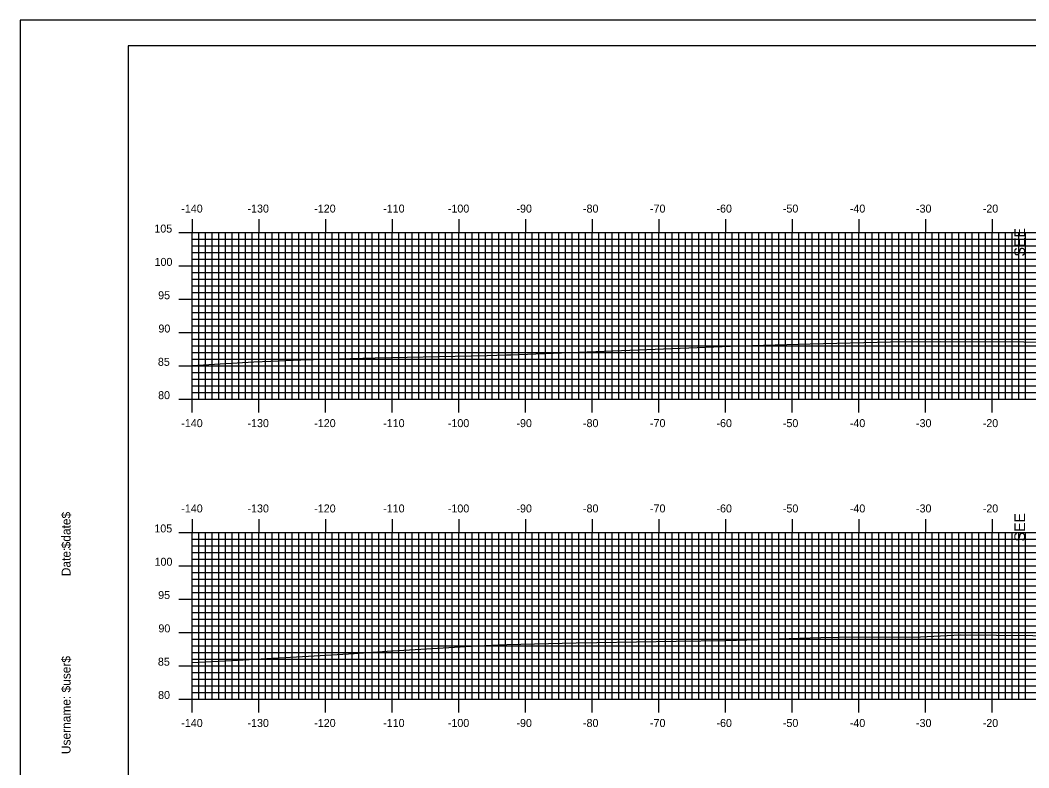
# Model space of a CAD drawing. Extents: x 1272 to 1616, y -1658 to -1438.
# Drawn here: x 1272.4 to 1423.7, y -1549.9 to -1437.7 of the extents above; entities that cross this region are included whole.
import ezdxf

# ---------------------------------------------------------------- set-up
doc = ezdxf.new("R2010")
doc.units = 0
for name, color, linetype in [('ANNOTATION', 7, 'Continuous'), ('BORDER', 7, 'Continuous'), ('H_V ANNOTATION', 7, 'Continuous'), ('MAJOR', 7, 'Continuous'), ('MINOR', 7, 'Continuous'), ('PLOT BOUNDARY', 7, 'Continuous'), ('S_Roadway_Centerline', 7, 'Continuous')]:
    doc.layers.add(name, color=color, linetype=linetype)

msp = doc.modelspace()

# ---------------------------------------------------------------- linework, layer by layer
at = {"layer": 'BORDER'}
msp.add_lwpolyline([(1288.56, -1651.6), (1608.56, -1651.6), (1608.56, -1441.6), (1288.56, -1441.6)], close=True, dxfattribs=at)
at = {"layer": 'MAJOR'}
for p, q in [((1298.16, -1467.6), (1298.16, -1469.6)), ((1308.16, -1467.6), (1308.16, -1469.6)), ((1318.16, -1467.6), (1318.16, -1469.6)), ((1328.16, -1467.6), (1328.16, -1469.6)), ((1338.16, -1467.6), (1338.16, -1469.6)), ((1348.16, -1467.6), (1348.16, -1469.6)), ((1358.16, -1467.6), (1358.16, -1469.6)), ((1368.16, -1467.6), (1368.16, -1469.6)), ((1378.16, -1467.6), (1378.16, -1469.6)), ((1388.16, -1467.6), (1388.16, -1469.6)), ((1398.16, -1467.6), (1398.16, -1469.6)), ((1408.16, -1467.6), (1408.16, -1469.6)), ((1418.16, -1467.6), (1418.16, -1469.6)), ((1296.16, -1469.6), (1298.16, -1469.6)), ((1298.16, -1469.6), (1578.16, -1469.6)), ((1298.16, -1494.6), (1298.16, -1469.6)), ((1298.16, -1494.6), (1298.16, -1469.6)), ((1298.16, -1469.6), (1578.16, -1469.6)), ((1308.16, -1494.6), (1308.16, -1469.6)), ((1318.16, -1494.6), (1318.16, -1469.6)), ((1328.16, -1494.6), (1328.16, -1469.6)), ((1338.16, -1494.6), (1338.16, -1469.6)), ((1348.16, -1494.6), (1348.16, -1469.6)), ((1358.16, -1494.6), (1358.16, -1469.6)), ((1368.16, -1494.6), (1368.16, -1469.6)), ((1378.16, -1494.6), (1378.16, -1469.6)), ((1388.16, -1494.6), (1388.16, -1469.6)), ((1398.16, -1494.6), (1398.16, -1469.6)), ((1408.16, -1494.6), (1408.16, -1469.6)), ((1418.16, -1494.6), (1418.16, -1469.6)), ((1296.16, -1474.6), (1298.16, -1474.6)), ((1298.16, -1474.6), (1578.16, -1474.6)), ((1296.16, -1479.6), (1298.16, -1479.6)), ((1298.16, -1479.6), (1578.16, -1479.6)), ((1296.16, -1484.6), (1298.16, -1484.6)), ((1298.16, -1484.6), (1578.16, -1484.6)), ((1296.16, -1489.6), (1298.16, -1489.6)), ((1298.16, -1489.6), (1578.16, -1489.6)), ((1296.16, -1494.6), (1298.16, -1494.6)), ((1298.16, -1494.6), (1578.16, -1494.6)), ((1298.16, -1494.6), (1578.16, -1494.6)), ((1298.16, -1496.61), (1298.16, -1494.6)), ((1308.16, -1496.61), (1308.16, -1494.6)), ((1318.16, -1496.61), (1318.16, -1494.6)), ((1328.16, -1496.61), (1328.16, -1494.6)), ((1338.16, -1496.61), (1338.16, -1494.6)), ((1348.16, -1496.61), (1348.16, -1494.6)), ((1358.16, -1496.61), (1358.16, -1494.6)), ((1368.16, -1496.61), (1368.16, -1494.6)), ((1378.16, -1496.61), (1378.16, -1494.6)), ((1388.16, -1496.61), (1388.16, -1494.6)), ((1398.16, -1496.61), (1398.16, -1494.6)), ((1408.16, -1496.61), (1408.16, -1494.6)), ((1418.16, -1496.61), (1418.16, -1494.6)), ((1298.16, -1512.6), (1298.16, -1514.6)), ((1308.16, -1512.6), (1308.16, -1514.6)), ((1318.16, -1512.6), (1318.16, -1514.6)), ((1328.16, -1512.6), (1328.16, -1514.6)), ((1338.16, -1512.6), (1338.16, -1514.6)), ((1348.16, -1512.6), (1348.16, -1514.6)), ((1358.16, -1512.6), (1358.16, -1514.6)), ((1368.16, -1512.6), (1368.16, -1514.6)), ((1378.16, -1512.6), (1378.16, -1514.6)), ((1388.16, -1512.6), (1388.16, -1514.6)), ((1398.16, -1512.6), (1398.16, -1514.6)), ((1408.16, -1512.6), (1408.16, -1514.6)), ((1418.16, -1512.6), (1418.16, -1514.6)), ((1296.16, -1514.6), (1298.16, -1514.6)), ((1298.16, -1514.6), (1578.16, -1514.6)), ((1298.16, -1539.6), (1298.16, -1514.6)), ((1298.16, -1539.6), (1298.16, -1514.6)), ((1298.16, -1514.6), (1578.16, -1514.6)), ((1308.16, -1539.6), (1308.16, -1514.6)), ((1318.16, -1539.6), (1318.16, -1514.6)), ((1328.16, -1539.6), (1328.16, -1514.6)), ((1338.16, -1539.6), (1338.16, -1514.6)), ((1348.16, -1539.6), (1348.16, -1514.6)), ((1358.16, -1539.6), (1358.16, -1514.6)), ((1368.16, -1539.6), (1368.16, -1514.6)), ((1378.16, -1539.6), (1378.16, -1514.6)), ((1388.16, -1539.6), (1388.16, -1514.6)), ((1398.16, -1539.6), (1398.16, -1514.6)), ((1408.16, -1539.6), (1408.16, -1514.6)), ((1418.16, -1539.6), (1418.16, -1514.6)), ((1296.16, -1519.6), (1298.16, -1519.6)), ((1298.16, -1519.6), (1578.16, -1519.6)), ((1296.16, -1524.6), (1298.16, -1524.6)), ((1298.16, -1524.6), (1578.16, -1524.6)), ((1296.16, -1529.6), (1298.16, -1529.6)), ((1298.16, -1529.6), (1578.16, -1529.6)), ((1296.16, -1534.6), (1298.16, -1534.6)), ((1298.16, -1534.6), (1578.16, -1534.6)), ((1296.16, -1539.6), (1298.16, -1539.6)), ((1298.16, -1539.6), (1578.16, -1539.6)), ((1298.16, -1539.6), (1578.16, -1539.6)), ((1298.16, -1541.61), (1298.16, -1539.6)), ((1308.16, -1541.61), (1308.16, -1539.6)), ((1318.16, -1541.61), (1318.16, -1539.6)), ((1328.16, -1541.61), (1328.16, -1539.6)), ((1338.16, -1541.61), (1338.16, -1539.6)), ((1348.16, -1541.61), (1348.16, -1539.6)), ((1358.16, -1541.61), (1358.16, -1539.6)), ((1368.16, -1541.61), (1368.16, -1539.6)), ((1378.16, -1541.61), (1378.16, -1539.6)), ((1388.16, -1541.61), (1388.16, -1539.6)), ((1398.16, -1541.61), (1398.16, -1539.6)), ((1408.16, -1541.61), (1408.16, -1539.6)), ((1418.16, -1541.61), (1418.16, -1539.6))]:
    msp.add_line(p, q, dxfattribs=at)
at = {"layer": 'MINOR'}
for p, q in [((1299.16, -1494.6), (1299.16, -1469.6)), ((1300.16, -1494.6), (1300.16, -1469.6)), ((1301.16, -1494.6), (1301.16, -1469.6)), ((1302.16, -1494.6), (1302.16, -1469.6)), ((1303.16, -1494.6), (1303.16, -1469.6)), ((1304.16, -1494.6), (1304.16, -1469.6)), ((1305.16, -1494.6), (1305.16, -1469.6)), ((1306.16, -1494.6), (1306.16, -1469.6)), ((1307.16, -1494.6), (1307.16, -1469.6)), ((1309.16, -1494.6), (1309.16, -1469.6)), ((1310.16, -1494.6), (1310.16, -1469.6)), ((1311.16, -1494.6), (1311.16, -1469.6)), ((1312.16, -1494.6), (1312.16, -1469.6)), ((1313.16, -1494.6), (1313.16, -1469.6)), ((1314.16, -1494.6), (1314.16, -1469.6)), ((1315.16, -1494.6), (1315.16, -1469.6)), ((1316.16, -1494.6), (1316.16, -1469.6)), ((1317.16, -1494.6), (1317.16, -1469.6)), ((1319.16, -1494.6), (1319.16, -1469.6)), ((1320.16, -1494.6), (1320.16, -1469.6)), ((1321.16, -1494.6), (1321.16, -1469.6)), ((1322.16, -1494.6), (1322.16, -1469.6)), ((1323.16, -1494.6), (1323.16, -1469.6)), ((1324.16, -1494.6), (1324.16, -1469.6)), ((1325.16, -1494.6), (1325.16, -1469.6)), ((1326.16, -1494.6), (1326.16, -1469.6)), ((1327.16, -1494.6), (1327.16, -1469.6)), ((1329.16, -1494.6), (1329.16, -1469.6)), ((1330.16, -1494.6), (1330.16, -1469.6)), ((1331.16, -1494.6), (1331.16, -1469.6)), ((1332.16, -1494.6), (1332.16, -1469.6)), ((1333.16, -1494.6), (1333.16, -1469.6)), ((1334.16, -1494.6), (1334.16, -1469.6)), ((1335.16, -1494.6), (1335.16, -1469.6)), ((1336.16, -1494.6), (1336.16, -1469.6)), ((1337.16, -1494.6), (1337.16, -1469.6)), ((1339.16, -1494.6), (1339.16, -1469.6)), ((1340.16, -1494.6), (1340.16, -1469.6)), ((1341.16, -1494.6), (1341.16, -1469.6)), ((1342.16, -1494.6), (1342.16, -1469.6)), ((1343.16, -1494.6), (1343.16, -1469.6)), ((1344.16, -1494.6), (1344.16, -1469.6)), ((1345.16, -1494.6), (1345.16, -1469.6)), ((1346.16, -1494.6), (1346.16, -1469.6)), ((1347.16, -1494.6), (1347.16, -1469.6)), ((1349.16, -1494.6), (1349.16, -1469.6)), ((1350.16, -1494.6), (1350.16, -1469.6)), ((1351.16, -1494.6), (1351.16, -1469.6)), ((1352.16, -1494.6), (1352.16, -1469.6)), ((1353.16, -1494.6), (1353.16, -1469.6)), ((1354.16, -1494.6), (1354.16, -1469.6)), ((1355.16, -1494.6), (1355.16, -1469.6)), ((1356.16, -1494.6), (1356.16, -1469.6)), ((1357.16, -1494.6), (1357.16, -1469.6)), ((1359.16, -1494.6), (1359.16, -1469.6)), ((1360.16, -1494.6), (1360.16, -1469.6)), ((1361.16, -1494.6), (1361.16, -1469.6)), ((1362.16, -1494.6), (1362.16, -1469.6)), ((1363.16, -1494.6), (1363.16, -1469.6)), ((1364.16, -1494.6), (1364.16, -1469.6)), ((1365.16, -1494.6), (1365.16, -1469.6)), ((1366.16, -1494.6), (1366.16, -1469.6)), ((1367.16, -1494.6), (1367.16, -1469.6)), ((1369.16, -1494.6), (1369.16, -1469.6)), ((1370.16, -1494.6), (1370.16, -1469.6)), ((1371.16, -1494.6), (1371.16, -1469.6)), ((1372.16, -1494.6), (1372.16, -1469.6)), ((1373.16, -1494.6), (1373.16, -1469.6)), ((1374.16, -1494.6), (1374.16, -1469.6)), ((1375.16, -1494.6), (1375.16, -1469.6)), ((1376.16, -1494.6), (1376.16, -1469.6)), ((1377.16, -1494.6), (1377.16, -1469.6)), ((1379.16, -1494.6), (1379.16, -1469.6)), ((1380.16, -1494.6), (1380.16, -1469.6)), ((1381.16, -1494.6), (1381.16, -1469.6)), ((1382.16, -1494.6), (1382.16, -1469.6)), ((1383.16, -1494.6), (1383.16, -1469.6)), ((1384.16, -1494.6), (1384.16, -1469.6)), ((1385.16, -1494.6), (1385.16, -1469.6)), ((1386.16, -1494.6), (1386.16, -1469.6)), ((1387.16, -1494.6), (1387.16, -1469.6)), ((1389.16, -1494.6), (1389.16, -1469.6)), ((1390.16, -1494.6), (1390.16, -1469.6)), ((1391.16, -1494.6), (1391.16, -1469.6)), ((1392.16, -1494.6), (1392.16, -1469.6)), ((1393.16, -1494.6), (1393.16, -1469.6)), ((1394.16, -1494.6), (1394.16, -1469.6)), ((1395.16, -1494.6), (1395.16, -1469.6)), ((1396.16, -1494.6), (1396.16, -1469.6)), ((1397.16, -1494.6), (1397.16, -1469.6)), ((1399.16, -1494.6), (1399.16, -1469.6)), ((1400.16, -1494.6), (1400.16, -1469.6)), ((1401.16, -1494.6), (1401.16, -1469.6)), ((1402.16, -1494.6), (1402.16, -1469.6)), ((1403.16, -1494.6), (1403.16, -1469.6)), ((1404.16, -1494.6), (1404.16, -1469.6)), ((1405.16, -1494.6), (1405.16, -1469.6)), ((1406.16, -1494.6), (1406.16, -1469.6)), ((1407.16, -1494.6), (1407.16, -1469.6)), ((1409.16, -1494.6), (1409.16, -1469.6)), ((1410.16, -1494.6), (1410.16, -1469.6)), ((1411.16, -1494.6), (1411.16, -1469.6)), ((1412.16, -1494.6), (1412.16, -1469.6)), ((1413.16, -1494.6), (1413.16, -1469.6)), ((1414.16, -1494.6), (1414.16, -1469.6)), ((1415.16, -1494.6), (1415.16, -1469.6)), ((1416.16, -1494.6), (1416.16, -1469.6)), ((1417.16, -1494.6), (1417.16, -1469.6)), ((1419.16, -1494.6), (1419.16, -1469.6)), ((1420.16, -1494.6), (1420.16, -1469.6)), ((1421.16, -1494.6), (1421.16, -1469.6)), ((1422.16, -1494.6), (1422.16, -1469.6)), ((1423.16, -1494.6), (1423.16, -1469.6)), ((1298.16, -1470.6), (1578.16, -1470.6)), ((1298.16, -1470.6), (1300.16, -1470.6)), ((1298.16, -1471.6), (1578.16, -1471.6)), ((1298.16, -1471.6), (1300.16, -1471.6)), ((1298.16, -1472.6), (1578.16, -1472.6)), ((1298.16, -1472.6), (1300.16, -1472.6)), ((1298.16, -1473.6), (1578.16, -1473.6)), ((1298.16, -1473.6), (1300.16, -1473.6)), ((1298.16, -1475.6), (1578.16, -1475.6)), ((1298.16, -1475.6), (1300.16, -1475.6)), ((1298.16, -1476.6), (1578.16, -1476.6)), ((1298.16, -1476.6), (1300.16, -1476.6)), ((1298.16, -1477.6), (1578.16, -1477.6)), ((1298.16, -1477.6), (1300.16, -1477.6)), ((1298.16, -1478.6), (1578.16, -1478.6)), ((1298.16, -1478.6), (1300.16, -1478.6)), ((1298.16, -1480.6), (1578.16, -1480.6)), ((1298.16, -1480.6), (1300.16, -1480.6)), ((1298.16, -1481.6), (1578.16, -1481.6)), ((1298.16, -1481.6), (1300.16, -1481.6)), ((1298.16, -1482.6), (1578.16, -1482.6)), ((1298.16, -1482.6), (1300.16, -1482.6)), ((1298.16, -1483.6), (1578.16, -1483.6)), ((1298.16, -1483.6), (1300.16, -1483.6)), ((1298.16, -1485.6), (1578.16, -1485.6)), ((1298.16, -1485.6), (1300.16, -1485.6)), ((1298.16, -1486.6), (1578.16, -1486.6)), ((1298.16, -1486.6), (1300.16, -1486.6)), ((1298.16, -1487.6), (1578.16, -1487.6)), ((1298.16, -1487.6), (1300.16, -1487.6)), ((1298.16, -1488.6), (1578.16, -1488.6)), ((1298.16, -1488.6), (1300.16, -1488.6)), ((1298.16, -1490.6), (1578.16, -1490.6)), ((1298.16, -1490.6), (1300.16, -1490.6)), ((1298.16, -1491.6), (1578.16, -1491.6)), ((1298.16, -1491.6), (1300.16, -1491.6)), ((1298.16, -1492.6), (1578.16, -1492.6)), ((1298.16, -1492.6), (1300.16, -1492.6)), ((1298.16, -1493.6), (1578.16, -1493.6)), ((1298.16, -1493.6), (1300.16, -1493.6)), ((1298.16, -1515.6), (1578.16, -1515.6)), ((1298.16, -1515.6), (1300.16, -1515.6)), ((1299.16, -1539.6), (1299.16, -1514.6)), ((1300.16, -1539.6), (1300.16, -1514.6)), ((1301.16, -1539.6), (1301.16, -1514.6)), ((1302.16, -1539.6), (1302.16, -1514.6)), ((1303.16, -1539.6), (1303.16, -1514.6)), ((1304.16, -1539.6), (1304.16, -1514.6)), ((1305.16, -1539.6), (1305.16, -1514.6)), ((1306.16, -1539.6), (1306.16, -1514.6)), ((1307.16, -1539.6), (1307.16, -1514.6)), ((1309.16, -1539.6), (1309.16, -1514.6)), ((1310.16, -1539.6), (1310.16, -1514.6)), ((1311.16, -1539.6), (1311.16, -1514.6)), ((1312.16, -1539.6), (1312.16, -1514.6)), ((1313.16, -1539.6), (1313.16, -1514.6)), ((1314.16, -1539.6), (1314.16, -1514.6)), ((1315.16, -1539.6), (1315.16, -1514.6)), ((1316.16, -1539.6), (1316.16, -1514.6)), ((1317.16, -1539.6), (1317.16, -1514.6)), ((1319.16, -1539.6), (1319.16, -1514.6)), ((1320.16, -1539.6), (1320.16, -1514.6)), ((1321.16, -1539.6), (1321.16, -1514.6)), ((1322.16, -1539.6), (1322.16, -1514.6)), ((1323.16, -1539.6), (1323.16, -1514.6)), ((1324.16, -1539.6), (1324.16, -1514.6)), ((1325.16, -1539.6), (1325.16, -1514.6)), ((1326.16, -1539.6), (1326.16, -1514.6)), ((1327.16, -1539.6), (1327.16, -1514.6)), ((1329.16, -1539.6), (1329.16, -1514.6)), ((1330.16, -1539.6), (1330.16, -1514.6)), ((1331.16, -1539.6), (1331.16, -1514.6)), ((1332.16, -1539.6), (1332.16, -1514.6)), ((1333.16, -1539.6), (1333.16, -1514.6)), ((1334.16, -1539.6), (1334.16, -1514.6)), ((1335.16, -1539.6), (1335.16, -1514.6)), ((1336.16, -1539.6), (1336.16, -1514.6)), ((1337.16, -1539.6), (1337.16, -1514.6)), ((1339.16, -1539.6), (1339.16, -1514.6)), ((1340.16, -1539.6), (1340.16, -1514.6)), ((1341.16, -1539.6), (1341.16, -1514.6)), ((1342.16, -1539.6), (1342.16, -1514.6)), ((1343.16, -1539.6), (1343.16, -1514.6)), ((1344.16, -1539.6), (1344.16, -1514.6)), ((1345.16, -1539.6), (1345.16, -1514.6)), ((1346.16, -1539.6), (1346.16, -1514.6)), ((1347.16, -1539.6), (1347.16, -1514.6)), ((1349.16, -1539.6), (1349.16, -1514.6)), ((1350.16, -1539.6), (1350.16, -1514.6)), ((1351.16, -1539.6), (1351.16, -1514.6)), ((1352.16, -1539.6), (1352.16, -1514.6)), ((1353.16, -1539.6), (1353.16, -1514.6)), ((1354.16, -1539.6), (1354.16, -1514.6)), ((1355.16, -1539.6), (1355.16, -1514.6)), ((1356.16, -1539.6), (1356.16, -1514.6)), ((1357.16, -1539.6), (1357.16, -1514.6)), ((1359.16, -1539.6), (1359.16, -1514.6)), ((1360.16, -1539.6), (1360.16, -1514.6)), ((1361.16, -1539.6), (1361.16, -1514.6)), ((1362.16, -1539.6), (1362.16, -1514.6)), ((1363.16, -1539.6), (1363.16, -1514.6)), ((1364.16, -1539.6), (1364.16, -1514.6)), ((1365.16, -1539.6), (1365.16, -1514.6)), ((1366.16, -1539.6), (1366.16, -1514.6)), ((1367.16, -1539.6), (1367.16, -1514.6)), ((1369.16, -1539.6), (1369.16, -1514.6)), ((1370.16, -1539.6), (1370.16, -1514.6)), ((1371.16, -1539.6), (1371.16, -1514.6)), ((1372.16, -1539.6), (1372.16, -1514.6)), ((1373.16, -1539.6), (1373.16, -1514.6)), ((1374.16, -1539.6), (1374.16, -1514.6)), ((1375.16, -1539.6), (1375.16, -1514.6)), ((1376.16, -1539.6), (1376.16, -1514.6)), ((1377.16, -1539.6), (1377.16, -1514.6)), ((1379.16, -1539.6), (1379.16, -1514.6)), ((1380.16, -1539.6), (1380.16, -1514.6)), ((1381.16, -1539.6), (1381.16, -1514.6)), ((1382.16, -1539.6), (1382.16, -1514.6)), ((1383.16, -1539.6), (1383.16, -1514.6)), ((1384.16, -1539.6), (1384.16, -1514.6)), ((1385.16, -1539.6), (1385.16, -1514.6)), ((1386.16, -1539.6), (1386.16, -1514.6)), ((1387.16, -1539.6), (1387.16, -1514.6)), ((1389.16, -1539.6), (1389.16, -1514.6)), ((1390.16, -1539.6), (1390.16, -1514.6)), ((1391.16, -1539.6), (1391.16, -1514.6)), ((1392.16, -1539.6), (1392.16, -1514.6)), ((1393.16, -1539.6), (1393.16, -1514.6)), ((1394.16, -1539.6), (1394.16, -1514.6)), ((1395.16, -1539.6), (1395.16, -1514.6)), ((1396.16, -1539.6), (1396.16, -1514.6)), ((1397.16, -1539.6), (1397.16, -1514.6)), ((1399.16, -1539.6), (1399.16, -1514.6)), ((1400.16, -1539.6), (1400.16, -1514.6)), ((1401.16, -1539.6), (1401.16, -1514.6)), ((1402.16, -1539.6), (1402.16, -1514.6)), ((1403.16, -1539.6), (1403.16, -1514.6)), ((1404.16, -1539.6), (1404.16, -1514.6)), ((1405.16, -1539.6), (1405.16, -1514.6)), ((1406.16, -1539.6), (1406.16, -1514.6)), ((1407.16, -1539.6), (1407.16, -1514.6)), ((1409.16, -1539.6), (1409.16, -1514.6)), ((1410.16, -1539.6), (1410.16, -1514.6)), ((1411.16, -1539.6), (1411.16, -1514.6)), ((1412.16, -1539.6), (1412.16, -1514.6)), ((1413.16, -1539.6), (1413.16, -1514.6)), ((1414.16, -1539.6), (1414.16, -1514.6)), ((1415.16, -1539.6), (1415.16, -1514.6)), ((1416.16, -1539.6), (1416.16, -1514.6)), ((1417.16, -1539.6), (1417.16, -1514.6)), ((1419.16, -1539.6), (1419.16, -1514.6)), ((1420.16, -1539.6), (1420.16, -1514.6)), ((1421.16, -1539.6), (1421.16, -1514.6)), ((1422.16, -1539.6), (1422.16, -1514.6)), ((1423.16, -1539.6), (1423.16, -1514.6)), ((1298.16, -1516.6), (1578.16, -1516.6)), ((1298.16, -1516.6), (1300.16, -1516.6)), ((1298.16, -1517.6), (1578.16, -1517.6)), ((1298.16, -1517.6), (1300.16, -1517.6)), ((1298.16, -1518.6), (1578.16, -1518.6)), ((1298.16, -1518.6), (1300.16, -1518.6)), ((1298.16, -1520.6), (1578.16, -1520.6)), ((1298.16, -1520.6), (1300.16, -1520.6)), ((1298.16, -1521.6), (1578.16, -1521.6)), ((1298.16, -1521.6), (1300.16, -1521.6)), ((1298.16, -1522.6), (1578.16, -1522.6)), ((1298.16, -1522.6), (1300.16, -1522.6)), ((1298.16, -1523.6), (1578.16, -1523.6)), ((1298.16, -1523.6), (1300.16, -1523.6)), ((1298.16, -1525.6), (1578.16, -1525.6)), ((1298.16, -1525.6), (1300.16, -1525.6)), ((1298.16, -1526.6), (1578.16, -1526.6)), ((1298.16, -1526.6), (1300.16, -1526.6)), ((1298.16, -1527.6), (1578.16, -1527.6)), ((1298.16, -1527.6), (1300.16, -1527.6)), ((1298.16, -1528.6), (1578.16, -1528.6)), ((1298.16, -1528.6), (1300.16, -1528.6)), ((1298.16, -1530.6), (1578.16, -1530.6)), ((1298.16, -1530.6), (1300.16, -1530.6)), ((1298.16, -1531.6), (1578.16, -1531.6)), ((1298.16, -1531.6), (1300.16, -1531.6)), ((1298.16, -1532.6), (1578.16, -1532.6)), ((1298.16, -1532.6), (1300.16, -1532.6)), ((1298.16, -1533.6), (1578.16, -1533.6)), ((1298.16, -1533.6), (1300.16, -1533.6)), ((1298.16, -1535.6), (1578.16, -1535.6)), ((1298.16, -1535.6), (1300.16, -1535.6)), ((1298.16, -1536.6), (1578.16, -1536.6)), ((1298.16, -1536.6), (1300.16, -1536.6)), ((1298.16, -1537.6), (1578.16, -1537.6)), ((1298.16, -1537.6), (1300.16, -1537.6)), ((1298.16, -1538.6), (1578.16, -1538.6)), ((1298.16, -1538.6), (1300.16, -1538.6))]:
    msp.add_line(p, q, dxfattribs=at)
at = {"layer": 'PLOT BOUNDARY'}
msp.add_lwpolyline([(1272.37, -1657.72), (1612.37, -1657.72), (1612.37, -1437.72), (1272.37, -1437.72)], close=True, dxfattribs=at)
at = {"layer": 'S_Roadway_Centerline'}
for points in [[(1298.16, -1489.57), (1298.19, -1489.57), (1307.43, -1489), (1309.98, -1488.88), (1314.49, -1488.71), (1325.64, -1488.38), (1342.41, -1488.04), (1345.3, -1487.96), (1345.97, -1487.93), (1347.17, -1487.89), (1365.12, -1487.18), (1378.93, -1486.65), (1382.04, -1486.54), (1383.87, -1486.51), (1390.85, -1486.29), (1402.89, -1485.98), (1410.44, -1485.94), (1422.9, -1486), (1430.31, -1486.16)], [(1298.16, -1534.12), (1304.06, -1533.83), (1317.35, -1533.07), (1322.46, -1532.75), (1327.44, -1532.42), (1340.88, -1531.63), (1345.37, -1531.42), (1355.79, -1531.19), (1358.86, -1531.14), (1370.78, -1530.9), (1378.2, -1530.8), (1392.45, -1530.39), (1395.19, -1530.32), (1407.39, -1530.27), (1413.4, -1529.96), (1429.64, -1530.1)]]:
    msp.add_lwpolyline(points, dxfattribs=at)

# ---------------------------------------------------------------- texts
at = {"layer": 'ANNOTATION'}
for p in [(1423.09, -1473.2), (1423.09, -1515.96)]:
    msp.add_text('SEE', height=1.6, rotation=90, dxfattribs=at).set_placement(p)
at = {"layer": 'BORDER'}
for s, p in [('$date$', (1279.93, -1516.99)), ('Date:', (1279.93, -1521.17)), ('$user$', (1279.93, -1538.62)), ('Username:', (1279.93, -1547.87))]:
    msp.add_text(s, height=1.339, rotation=90, dxfattribs=at).set_placement(p)
at = {"layer": 'H_V ANNOTATION'}
for s, p in [('-140', (1296.54, -1466.6)), ('-130', (1306.47, -1466.6)), ('-120', (1316.48, -1466.6)), ('-110', (1326.82, -1466.6)), ('-100', (1336.52, -1466.6)), ('-90', (1346.81, -1466.6)), ('-80', (1356.79, -1466.6)), ('-70', (1366.84, -1466.6)), ('-60', (1376.81, -1466.6)), ('-50', (1386.77, -1466.6)), ('-40', (1396.81, -1466.6)), ('-30', (1406.74, -1466.6)), ('-20', (1416.75, -1466.6)), ('105', (1292.5, -1469.6)), ('100', (1292.53, -1474.6)), ('95', (1293.07, -1479.6)), ('90', (1293.11, -1484.6)), ('85', (1293.03, -1489.6)), ('80', (1293.06, -1494.6)), ('-140', (1296.54, -1498.8)), ('-130', (1306.47, -1498.8)), ('-120', (1316.48, -1498.8)), ('-110', (1326.82, -1498.8)), ('-100', (1336.52, -1498.8)), ('-90', (1346.81, -1498.8)), ('-80', (1356.79, -1498.8)), ('-70', (1366.84, -1498.8)), ('-60', (1376.81, -1498.8)), ('-50', (1386.77, -1498.8)), ('-40', (1396.81, -1498.8)), ('-30', (1406.74, -1498.8)), ('-20', (1416.75, -1498.8)), ('-140', (1296.54, -1511.6)), ('-130', (1306.47, -1511.6)), ('-120', (1316.48, -1511.6)), ('-110', (1326.82, -1511.6)), ('-100', (1336.52, -1511.6)), ('-90', (1346.81, -1511.6)), ('-80', (1356.79, -1511.6)), ('-70', (1366.84, -1511.6)), ('-60', (1376.81, -1511.6)), ('-50', (1386.77, -1511.6)), ('-40', (1396.81, -1511.6)), ('-30', (1406.74, -1511.6)), ('-20', (1416.75, -1511.6)), ('105', (1292.5, -1514.6)), ('100', (1292.53, -1519.6)), ('95', (1293.07, -1524.6)), ('90', (1293.11, -1529.6)), ('85', (1293.03, -1534.6)), ('80', (1293.06, -1539.6)), ('-140', (1296.54, -1543.8)), ('-130', (1306.47, -1543.8)), ('-120', (1316.48, -1543.8)), ('-110', (1326.82, -1543.8)), ('-100', (1336.52, -1543.8)), ('-90', (1346.81, -1543.8)), ('-80', (1356.79, -1543.8)), ('-70', (1366.84, -1543.8)), ('-60', (1376.81, -1543.8)), ('-50', (1386.77, -1543.8)), ('-40', (1396.81, -1543.8)), ('-30', (1406.74, -1543.8)), ('-20', (1416.75, -1543.8))]:
    msp.add_text(s, height=1.2, dxfattribs=at).set_placement(p)
at = {"layer": 'MAJOR'}
for p in [(1298.15, -1494.6), (1298.15, -1539.6)]:
    msp.add_text('-', height=0.012, dxfattribs=at).set_placement(p)

doc.saveas('drawing.dxf')
